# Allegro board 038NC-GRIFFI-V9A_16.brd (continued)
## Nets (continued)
N05396: UNK2K6.4 UNK2R3.1
N05400: UNK2K5.4 UNK2R2.1
N05404: UNK2R41.2 UNK2R42.1
N05614: UNK2C5.1 UNK2K8.5
N05638: UNK2C3.1 UNK2K2.4
N05774: UNK2C4.2 UNK2K8.4
N05938: SITE2.S24(PVSS_S) UNK2RS2.2 UNK2RS4.2
N05964: UNK2R14.1 UNK2SH7.1 UNK2SH9.2 UNK2SH14.2 UNK2SH16.2 UNK2SH30.1 UNK2SH32.2
N05980: UNK2R13.1 UNK2SH2.1 UNK2SH20.1 UNK2SH29.1 UNK2SH33.1 UNK2SH34.1 UNK2SH39.2
N10483: UNK3K7.4 UNK3R41.1
N10487: UNK3K6.4 UNK3R3.1
N10491: UNK3K5.4 UNK3R2.1
N10495: UNK3R41.2 UNK3R42.1
N10705: UNK3C5.1 UNK3K8.5
N10729: UNK3C3.1 UNK3K2.4
N10865: UNK3C4.2 UNK3K8.4
N11029: SITE3.S24(PVSS_S) UNK3RS2.2 UNK3RS4.2
N11055: UNK3R14.1 UNK3SH7.1 UNK3SH9.2 UNK3SH14.2 UNK3SH16.2 UNK3SH30.1 UNK3SH32.2
N11071: UNK3R13.1 UNK3SH2.1 UNK3SH20.1 UNK3SH29.1 UNK3SH33.1 UNK3SH34.1 UNK3SH39.2
N15574: UNK4K7.4 UNK4R41.1
N15578: UNK4K6.4 UNK4R3.1
N15582: UNK4K5.4 UNK4R2.1
N15586: UNK4R41.2 UNK4R42.1
N15796: UNK4C5.1 UNK4K8.5
N15820: UNK4C3.1 UNK4K2.4
N15956: UNK4C4.2 UNK4K8.4
N16120: SITE4.S24(PVSS_S) UNK4RS2.2 UNK4RS4.2
N16146: UNK4R14.1 UNK4SH7.1 UNK4SH9.2 UNK4SH14.2 UNK4SH16.2 UNK4SH30.1 UNK4SH32.2
N16162: UNK4R13.1 UNK4SH2.1 UNK4SH20.1 UNK4SH29.1 UNK4SH33.1 UNK4SH34.1 UNK4SH39.2
N20665: UNK5K7.4 UNK5R41.1
N20669: UNK5K6.4 UNK5R3.1
N20673: UNK5K5.4 UNK5R2.1
N20677: UNK5R41.2 UNK5R42.1
N20887: UNK5C5.1 UNK5K8.5
N20911: UNK5C3.1 UNK5K2.4
N21047: UNK5C4.2 UNK5K8.4
N21211: SITE5.S24(PVSS_S) UNK5RS2.2 UNK5RS4.2
N21237: UNK5R14.1 UNK5SH7.1 UNK5SH9.2 UNK5SH14.2 UNK5SH16.2 UNK5SH30.1 UNK5SH32.2
N21253: UNK5R13.1 UNK5SH2.1 UNK5SH20.1 UNK5SH29.1 UNK5SH33.1 UNK5SH34.1 UNK5SH39.2
N25756: UNK6K7.4 UNK6R41.1
N25760: UNK6K6.4 UNK6R3.1
N25764: UNK6K5.4 UNK6R2.1
N25768: UNK6R41.2 UNK6R42.1
N25978: UNK6C5.1 UNK6K8.5
N26002: UNK6C3.1 UNK6K2.4
N26138: UNK6C4.2 UNK6K8.4
N26302: SITE6.S24(PVSS_S) UNK6RS2.2 UNK6RS4.2
N26328: UNK6R14.1 UNK6SH7.1 UNK6SH9.2 UNK6SH14.2 UNK6SH16.2 UNK6SH30.1 UNK6SH32.2
N26344: UNK6R13.1 UNK6SH2.1 UNK6SH20.1 UNK6SH29.1 UNK6SH33.1 UNK6SH34.1 UNK6SH39.2
N30847: UNK7K7.4 UNK7R41.1
N30851: UNK7K6.4 UNK7R3.1
N30855: UNK7K5.4 UNK7R2.1
N30859: UNK7R41.2 UNK7R42.1
N31069: UNK7C5.1 UNK7K8.5
N31093: UNK7C3.1 UNK7K2.4
N31229: UNK7C4.2 UNK7K8.4
N31393: SITE7.S24(PVSS_S) UNK7RS2.2 UNK7RS4.2
N31419: UNK7R14.1 UNK7SH7.1 UNK7SH9.2 UNK7SH14.2 UNK7SH16.2 UNK7SH30.1 UNK7SH32.2
N31435: UNK7R13.1 UNK7SH2.1 UNK7SH20.1 UNK7SH29.1 UNK7SH33.1 UNK7SH34.1 UNK7SH39.2
N35938: UNK8K7.4 UNK8R41.1
N35942: UNK8K6.4 UNK8R3.1
N35946: UNK8K5.4 UNK8R2.1
N35950: UNK8R41.2 UNK8R42.1
N36160: UNK8C5.1 UNK8K8.5
N36184: UNK8C3.1 UNK8K2.4
N36320: UNK8C4.2 UNK8K8.4
N36484: SITE8.S24(PVSS_S) UNK8RS2.2 UNK8RS4.2
N36510: UNK8R14.1 UNK8SH7.1 UNK8SH9.2 UNK8SH14.2 UNK8SH16.2 UNK8SH30.1 UNK8SH32.2
N36526: UNK8R13.1 UNK8SH2.1 UNK8SH20.1 UNK8SH29.1 UNK8SH33.1 UNK8SH34.1 UNK8SH39.2
N41029: UNK9K7.4 UNK9R41.1
N41033: UNK9K6.4 UNK9R3.1
N41037: UNK9K5.4 UNK9R2.1
N41041: UNK9R41.2 UNK9R42.1
N41251: UNK9C5.1 UNK9K8.5
N41275: UNK9C3.1 UNK9K2.4
N41411: UNK9C4.2 UNK9K8.4
N41575: SITE9.S24(PVSS_S) UNK9RS2.2 UNK9RS4.2
N41601: UNK9R14.1 UNK9SH7.1 UNK9SH9.2 UNK9SH14.2 UNK9SH16.2 UNK9SH30.1 UNK9SH32.2
N41617: UNK9R13.1 UNK9SH2.1 UNK9SH20.1 UNK9SH29.1 UNK9SH33.1 UNK9SH34.1 UNK9SH39.2
N46120: UNK10K7.4 UNK10R41.1
N46124: UNK10K6.4 UNK10R3.1
N46128: UNK10K5.4 UNK10R2.1
N46132: UNK10R41.2 UNK10R42.1
N46342: UNK10C5.1 UNK10K8.5
N46366: UNK10C3.1 UNK10K2.4
N46502: UNK10C4.2 UNK10K8.4
N46666: SITE10.S24(PVSS_S) UNK10RS2.2 UNK10RS4.2
N46692: UNK10R14.1 UNK10SH7.1 UNK10SH9.2 UNK10SH14.2 UNK10SH16.2 UNK10SH30.1 UNK10SH32.2
N46708: UNK10R13.1 UNK10SH2.1 UNK10SH20.1 UNK10SH29.1 UNK10SH33.1 UNK10SH34.1 UNK10SH39.2
N51211: UNK11K7.4 UNK11R41.1
N51215: UNK11K6.4 UNK11R3.1
N51219: UNK11K5.4 UNK11R2.1
N51223: UNK11R41.2 UNK11R42.1
N51433: UNK11C5.1 UNK11K8.5
N51457: UNK11C3.1 UNK11K2.4
N51593: UNK11C4.2 UNK11K8.4
N51757: SITE11.S24(PVSS_S) UNK11RS2.2 UNK11RS4.2
N51783: UNK11R14.1 UNK11SH7.1 UNK11SH9.2 UNK11SH14.2 UNK11SH16.2 UNK11SH30.1 UNK11SH32.2
N51799: UNK11R13.1 UNK11SH2.1 UNK11SH20.1 UNK11SH29.1 UNK11SH33.1 UNK11SH34.1 UNK11SH39.2
N56302: UNK12K7.4 UNK12R41.1
N56306: UNK12K6.4 UNK12R3.1
N56310: UNK12K5.4 UNK12R2.1
N56314: UNK12R41.2 UNK12R42.1
N56524: UNK12C5.1 UNK12K8.5
N56548: UNK12C3.1 UNK12K2.4
N56684: UNK12C4.2 UNK12K8.4
N56848: SITE12.S24(PVSS_S) UNK12RS2.2 UNK12RS4.2
N56874: UNK12R14.1 UNK12SH7.1 UNK12SH9.2 UNK12SH14.2 UNK12SH16.2 UNK12SH30.1 UNK12SH32.2
N56890: UNK12R13.1 UNK12SH2.1 UNK12SH20.1 UNK12SH29.1 UNK12SH33.1 UNK12SH34.1 UNK12SH39.2
N61393: UNK13K7.4 UNK13R41.1
N61397: UNK13K6.4 UNK13R3.1
N61401: UNK13K5.4 UNK13R2.1
N61405: UNK13R41.2 UNK13R42.1
N61615: UNK13C5.1 UNK13K8.5
N61639: UNK13C3.1 UNK13K2.4
N61775: UNK13C4.2 UNK13K8.4
N61939: SITE13.S24(PVSS_S) UNK13RS2.2 UNK13RS4.2
N61965: UNK13R14.1 UNK13SH7.1 UNK13SH9.2 UNK13SH14.2 UNK13SH16.2 UNK13SH30.1 UNK13SH32.2
N61981: UNK13R13.1 UNK13SH2.1 UNK13SH20.1 UNK13SH29.1 UNK13SH33.1 UNK13SH34.1 UNK13SH39.2
N66484: UNK14K7.4 UNK14R41.1
N66488: UNK14K6.4 UNK14R3.1
N66492: UNK14K5.4 UNK14R2.1
N66496: UNK14R41.2 UNK14R42.1
N66706: UNK14C5.1 UNK14K8.5
N66730: UNK14C3.1 UNK14K2.4
N66866: UNK14C4.2 UNK14K8.4
N67030: SITE14.S24(PVSS_S) UNK14RS2.2 UNK14RS4.2
N67056: UNK14R14.1 UNK14SH7.1 UNK14SH9.2 UNK14SH14.2 UNK14SH16.2 UNK14SH30.1 UNK14SH32.2
N67072: UNK14R13.1 UNK14SH2.1 UNK14SH20.1 UNK14SH29.1 UNK14SH33.1 UNK14SH34.1 UNK14SH39.2
N71575: UNK15K7.4 UNK15R41.1
N71579: UNK15K6.4 UNK15R3.1
N71583: UNK15K5.4 UNK15R2.1
N71587: UNK15R41.2 UNK15R42.1
N71797: UNK15C5.1 UNK15K8.5
N71821: UNK15C3.1 UNK15K2.4
N71957: UNK15C4.2 UNK15K8.4
N72121: SITE15.S24(PVSS_S) UNK15RS2.2 UNK15RS4.2
N72147: UNK15R14.1 UNK15SH7.1 UNK15SH9.2 UNK15SH14.2 UNK15SH16.2 UNK15SH30.1 UNK15SH32.2
N72163: UNK15R13.1 UNK15SH2.1 UNK15SH20.1 UNK15SH29.1 UNK15SH33.1 UNK15SH34.1 UNK15SH39.2
N76666: UNK16K7.4 UNK16R41.1
N76670: UNK16K6.4 UNK16R3.1
N76674: UNK16K5.4 UNK16R2.1
N76678: UNK16R41.2 UNK16R42.1
N76888: UNK16C5.1 UNK16K8.5
N76912: UNK16C3.1 UNK16K2.4
N77048: UNK16C4.2 UNK16K8.4
N77212: SITE16.S24(PVSS_S) UNK16RS2.2 UNK16RS4.2
N77238: UNK16R14.1 UNK16SH7.1 UNK16SH9.2 UNK16SH14.2 UNK16SH16.2 UNK16SH30.1 UNK16SH32.2
N77254: UNK16R13.1 UNK16SH2.1 UNK16SH20.1 UNK16SH29.1 UNK16SH33.1 UNK16SH34.1 UNK16SH39.2
N19416570: UNK1K7.4 UNK1R41.1
N19416573: UNK1K6.4 UNK1R3.1
N19416576: UNK1K5.4 UNK1R2.1
N19416583: UNK1R41.2 UNK1R42.1
N19419031: UNK1C5.1 UNK1K8.5
N19465903: UNK1C3.1 UNK1K2.4
N19474263: UNK1C4.2 UNK1K8.4
N19657625: SITE1.S24(PVSS_S) UNK1RS2.2 UNK1RS4.2
N19659235: UNK1R14.1 UNK1SH7.1 UNK1SH9.2 UNK1SH14.2 UNK1SH16.2 UNK1SH30.1 UNK1SH32.2
N19659515: UNK1R13.1 UNK1SH2.1 UNK1SH20.1 UNK1SH29.1 UNK1SH33.1 UNK1SH34.1 UNK1SH39.2
N22962297: BR4.1 USER_12V1.2(B)
N22962300: BR1.1 USER_5V1.2(B)
N22962303: BR2.1 USER_-5V1.2(B)
N22962306: BR3.1 RLY_5V1.2(B)

Pads without a net: FD1 1; FD2 1; FD3 1; FD4 1; FD5 1; FD6 1; FD7 1; FD8 1; FD9 1; FD10 1; FD11 1; FD12 1; FD13 1; FD14 1; FD15 1; FD16 1; LOGO1 1; LOGO2 1; NPM1212-GRIFFI 1; NPM1212-QFN28-P0.4 1; SITE1 NUT1 NUT2 NUT3 NUT4; SITE2 NUT1 NUT2 NUT3 NUT4; SITE3 NUT1 NUT2 NUT3 NUT4; SITE4 NUT1 NUT2 NUT3 NUT4; SITE5 NUT1 NUT2 NUT3 NUT4; SITE6 NUT1 NUT2 NUT3 NUT4; SITE7 NUT1 NUT2 NUT3 NUT4; SITE8 NUT1 NUT2 NUT3 NUT4; SITE9 NUT1 NUT2 NUT3 NUT4; SITE10 NUT1 NUT2 NUT3 NUT4; SITE11 NUT1 NUT2 NUT3 NUT4; SITE12 NUT1 NUT2 NUT3 NUT4; SITE13 NUT1 NUT2 NUT3 NUT4; SITE14 NUT1 NUT2 NUT3 NUT4; SITE15 NUT1 NUT2 NUT3 NUT4; SITE16 NUT1 NUT2 NUT3 NUT4; SLOT0 A1 A48 B1 C1 D1 E1 F1 G48 Z5 Z7 Z9 Z11 Z13 Z15 Z17 Z19 Z21 Z23 Z25 Z27 Z29 Z31 Z33 Z35 Z37 Z39 Z41 Z43 Z45 Z47 Z49 Z51 Z53 Z55 Z57 Z59 Z61; SLOT1 A1 A2 A3 A4 A5 A6 A7 A8 A9 A10 A11 A12 A13 A14 A15 A16 A17 A18 A19 A20 A21 A22 A23 A24 A25 A26 A27 A28 A29 A30 A31 A32 A33 A34 A35 A36 A37 A38 A39 A40 A41 A42 A43 A44 A45 A46 A47 A48 A49 A50 A51 A52 A53 A54 A55 A56 A57 A58 A59 A60 A61 B1 B2 B3 B4 B5 B6 B7 B8 B9 B10 B11 B12 B13 B14 B15 B16 B17 B18 B19 B20 B21 B22 B23 B24 B25 B26 B27 B28 B29 B30 B31 B32 B33 B34 B35 B36 B37 B38 B39 B40 B41 B42 B43 B44 B45 B46 B47 B48 B49 B50 B51 B52 B53 B54 B55 B56 B57 B58 B59 B60 B61 B62 C1 C2 C3 C4 C5 C6 C7 C8 C9 C10 C11 C12 C13 C14 C15 C16 C17 C18 C19 C20 C21 C22 C23 C24 C25 C26 C27 C28 C29 C30 C31 C32 C33 C34 C35 C36 C37 C38 C39 C40 C41 C42 C43 C44 C45 C46 C47 C48 C49 C50 C51 C52 C53 C54 C55 C56 C57 C58 C59 C60 C61 C62 D1 D2 D3 D4 D5 D6 D7 D8 D9 D10 D11 D12 D13 D14 D15 D16 D17 D18 D19 D20 D21 D22 D23 D24 D25 D26 D27 D28 D29 D30 D31 D32 D33 D34 D35 D36 D37 D38 D39 D40 D41 D42 D43 D44 D45 D46 D47 D48 D49 D50 D51 D52 D53 D54 D55 D56 D57 D58 D59 D60 D61 E1 E2 E3 E4 E5 E6 E7 E8 E9 E10 E11 E12 E13 E14 E15 E16 E17 E18 E19 E20 E21 E22 E23 E24 E25 E26 E27 E28 E29 E30 E31 E32 E33 E34 E35 E36 E37 E38 E39 E40 E41 E42 E43 E44 E45 E46 E47 E48 E49 E50 E51 E52 E53 E54 E55 E56 E57 E58 E59 E60 E61 E62 F1 F2 F3 F4 F5 F6 F7 F8 F9 F10 F11 F12 F13 F14 F15 F16 F17 F18 F19 F20 F21 F22 F23 F24 F25 F26 F27 F28 F29 F30 F31 F32 F33 F34 F35 F36 F37 F38 F39 F40 F41 F42 F43 F44 F45 F46 F47 F48 F49 F50 F51 F52 F53 F54 F55 F56 F57 F58 F59 F60 F61 F62 G2 G4 G6 G8 G10 G12 G14 G16 G18 G20 G22 G24 G26 G28 G30 G32 G34 G36 G38 G40 G42 G44 G46 G48 G50 G52 G54 G56 G58 G60 Z5 Z7 Z9 Z11 Z13 Z15 Z17 Z19 Z21 Z23 Z25 Z27 Z29 Z31 Z33 Z35 Z37 Z39 Z41 Z43 Z45 Z47 Z49 Z51 Z53 Z55 Z57 Z59 Z61; SLOT2 A1 A2 A3 A4 A5 A6 A7 A8 A9 A10 A11 A12 A13 A14 A15 A16 A17 A18 A19 A20 A21 A22 A23 A24 A25 A26 A27 A28 A29 A30 A31 A32 A33 A34 A35 A36 A37 A38 A39 A40 A41 A42 A43 A44 A45 A46 A47 A48 A49 A50 A51 A52 A53 A54 A55 A56 A57 A58 A59 A60 A61 B1 B2 B3 B4 B5 B6 B7 B8 B9 B10 B11 B12 B13 B14 B15 B16 B17 B18 B19 B20 B21 B22 B23 B24 B25 B26 B27 B28 B29 B30 B31 B32 B33 B34 B35 B36 B37 B38 B39 B40 B41 B42 B43 B44 B45 B46 B47 B48 B49 B50 B51 B52 B53 B54 B55 B56 B57 B58 B59 B60 B61 B62 C1 C2 C3 C4 C5 C6 C7 C8 C9 C10 C11 C12 C13 C14 C15 C16 C17 C18 C19 C20 C21 C22 C23 C24 C25 C26 C27 C28 C29 C30 C31 C32 C33 C34 C35 C36 C37 C38 C39 C40 C41 C42 C43 C44 C45 C46 C47 C48 C49 C50 C51 C52 C53 C54 C55 C56 C57 C58 C59 C60 C61 C62 D1 D2 D3 D4 D5 D6 D7 D8 D9 D10 D11 D12 D13 D14 D15 D16 D17 D18 D19 D20 D21 D22 D23 D24 D25 D26 D27 D28 D29 D30 D31 D32 D33 D34 D35 D36 D37 D38 D39 D40 D41 D42 D43 D44 D45 D46 D47 D48 D49 D50 D51 D52 D53 D54 D55 D56 D57 D58 D59 D60 D61 E1 E2 E3 E4 E5 E6 E7 E8 E9 E10 E11 E12 E13 E14 E15 E16 E17 E18 E19 E20 E21 E22 E23 E24 E25 E26 E27 E28 E29 E30 E31 E32 E33 E34 E35 E36 E37 E38 E39 E40 E41 E42 E43 E44 E45 E46 E47 E48 E49 E50 E51 E52 E53 E54 E55 E56 E57 E58 E59 E60 E61 E62 F1 F2 F3 F4 F5 F6 F7 F8 F9 F10 F11 F12 F13 F14 F15 F16 F17 F18 F19 F20 F21 F22 F23 F24 F25 F26 F27 F28 F29 F30 F31 F32 F33 F34 F35 F36 F37 F38 F39 F40 F41 F42 F43 F44 F45 F46 F47 F48 F49 F50 F51 F52 F53 F54 F55 F56 F57 F58 F59 F60 F61 F62 G2 G4 G6 G8 G10 G12 G14 G16 G18 G20 G22 G24 G26 G28 G30 G32 G34 G36 G38 G40 G42 G44 G46 G48 G50 G52 G54 G56 G58 G60 Z5 Z7 Z9 Z11 Z13 Z15 Z17 Z19 Z21 Z23 Z25 Z27 Z29 Z31 Z33 Z35 Z37 Z39 Z41 Z43 Z45 Z47 Z49 Z51 Z53 Z55 Z57 Z59 Z61; SLOT3 A1 A2 A3 A4 A19 A61 B1 B2 B3 B4 B61 B62 C1 C2 C3 C4 C62 D1 D2 D3 D4 D19 E1 E2 E3 E4 E19 E62 F1 F2 F3 F4 F62 G2 G4 G6 G8 G10 G12 G14 G16 G18 G20 G22 G24 G26 G28 G30 G32 G34 G36 G38 G40 G42 G44 G46 G48 G50 G52 G54 G56 G58 G60 Z17 Z19 Z37 Z51 Z61; SLOT4 A1 A2 A3 A4 A19 A61 B1 B2 B3 B4 B61 B62 C1 C2 C3 C4 C62 D1 D2 D3 D4 D19 E1 E2 E3 E4 E19 E62 F1 F2 F3 F4 F62 G2 G4 G6 G8 G10 G12 G14 G16 G18 G20 G22 G24 G26 G28 G30 G32 G34 G36 G38 G40 G42 G44 G46 G48 G50 G52 G54 G56 G58 G60 Z17 Z19 Z37 Z51 Z61; SLOT5 A1 A2 A3 A4 A5 A6 A7 A8 A9 A10 A11 A12 A13 A14 A15 A16 A17 A18 A19 A20 A21 A22 A23 A24 A25 A26 A27 A28 A29 A30 A31 A32 A33 A34 A35 A36 A37 A38 A39 A40 A41 A42 A43 A44 A45 A46 A47 A48 A49 A50 A51 A52 A53 A54 A55 A56 A57 A58 A59 A60 A61 B1 B2 B3 B4 B5 B6 B7 B8 B9 B10 B11 B12 B13 B14 B15 B16 B17 B18 B19 B20 B21 B22 B23 B24 B25 B26 B27 B28 B29 B30 B31 B32 B33 B34 B35 B36 B37 B38 B39 B40 B41 B42 B43 B44 B45 B46 B47 B48 B49 B50 B51 B52 B53 B54 B55 B56 B57 B58 B59 B60 B61 B62 C1 C2 C3 C4 C5 C6 C7 C8 C9 C10 C11 C12 C13 C14 C15 C16 C17 C18 C19 C20 C21 C22 C23 C24 C25 C26 C27 C28 C29 C30 C31 C32 C33 C34 C35 C36 C37 C38 C39 C40 C41 C42 C43 C44 C45 C46 C47 C48 C49 C50 C51 C52 C53 C54 C55 C56 C57 C58 C59 C60 C61 C62 D1 D2 D3 D4 D5 D6 D7 D8 D9 D10 D11 D12 D13 D14 D15 D16 D17 D18 D19 D20 D21 D22 D23 D24 D25 D26 D27 D28 D29 D30 D31 D32 D33 D34 D35 D36 D37 D38 D39 D40 D41 D42 D43 D44 D45 D46 D47 D48 D49 D50 D51 D52 D53 D54 D55 D56 D57 D58 D59 D60 D61 E1 E2 E3 E4 E5 E6 E7 E8 E9 E10 E11 E12 E13 E14 E15 E16 E17 E18 E19 E20 E21 E22 E23 E24 E25 E26 E27 E28 E29 E30 E31 E32 E33 E34 E35 E36 E37 E38 E39 E40 E41 E42 E43 E44 E45 E46 E47 E48 E49 E50 E51 E52 E53 E54 E55 E56 E57 E58 E59 E60 E61 E62 F1 F2 F3 F4 F5 F6 F7 F8 F9 F10 F11 F12 F13 F14 F15 F16 F17 F18 F19 F20 F21 F22 F23 F24 F25 F26 F27 F28 F29 F30 F31 F32 F33 F34 F35 F36 F37 F38 F39 F40 F41 F42 F43 F44 F45 F46 F47 F48 F49 F50 F51 F52 F53 F54 F55 F56 F57 F58 F59 F60 F61 F62 G2 G4 G6 G8 G10 G12 G14 G16 G18 G20 G22 G24 G26 G28 G30 G32 G34 G36 G38 G40 G42 G44 G46 G48 G50 G52 G54 G56 G58 G60 Z5 Z7 Z9 Z11 Z13 Z15 Z17 Z19 Z21 Z23 Z25 Z27 Z29 Z31 Z33 Z35 Z37 Z39 Z41 Z43 Z45 Z47 Z49 Z51 Z53 Z55 Z57 Z59 Z61; SLOT6 B6 D6 D23 D27 D31 D35 E4 Z5 Z7 Z9 Z11 Z13 Z15 Z17 Z19 Z21 Z23 Z25 Z27 Z29 Z31 Z33 Z35 Z37 Z39 Z41 Z43 Z45 Z47 Z49 Z51 Z53 Z55 Z57 Z59 Z61; SLOT7 B6 D6 D23 D27 D31 D35 E4 Z5 Z7 Z9 Z11 Z13 Z15 Z17 Z19 Z21 Z23 Z25 Z27 Z29 Z31 Z33 Z35 Z37 Z39 Z41 Z43 Z45 Z47 Z49 Z51 Z53 Z55 Z57 Z59 Z61; SLOT8 B6 D6 D23 D27 D31 D35 E4 Z5 Z7 Z9 Z11 Z13 Z15 Z17 Z19 Z21 Z23 Z25 Z27 Z29 Z31 Z33 Z35 Z37 Z39 Z41 Z43 Z45 Z47 Z49 Z51 Z53 Z55 Z57 Z59 Z61; SLOT9 B6 D6 D23 D27 D31 D35 E4 Z5 Z7 Z9 Z11 Z13 Z15 Z17 Z19 Z21 Z23 Z25 Z27 Z29 Z31 Z33 Z35 Z37 Z39 Z41 Z43 Z45 Z47 Z49 Z51 Z53 Z55 Z57 Z59 Z61; SLOT10 B6 D6 D23 D27 D31 D35 E4 Z5 Z7 Z9 Z11 Z13 Z15 Z17 Z19 Z21 Z23 Z25 Z27 Z29 Z31 Z33 Z35 Z37 Z39 Z41 Z43 Z45 Z47 Z49 Z51 Z53 Z55 Z57 Z59 Z61; SLOT11 A1 A2 A3 A4 A5 A6 A7 A8 A9 A10 A11 A12 A13 A14 A15 A16 A17 A18 A19 A20 A21 A22 A23 A24 A25 A26 A27 A28 A29 A30 A31 A32 A33 A34 A35 A36 A37 A38 A39 A40 A41 A42 A43 A44 A45 A46 A47 A48 A49 A50 A51 A52 A53 A54 A55 A56 A57 A58 A59 A60 A61 B1 B2 B3 B4 B5 B6 B7 B8 B9 B10 B11 B12 B13 B14 B15 B16 B17 B18 B19 B20 B21 B22 B23 B24 B25 B26 B27 B28 B29 B30 B31 B32 B33 B34 B35 B36 B37 B38 B39 B40 B41 B42 B43 B44 B45 B46 B47 B48 B49 B50 B51 B52 B53 B54 B55 B56 B57 B58 B59 B60 B61 B62 C1 C2 C3 C4 C5 C6 C7 C8 C9 C10 C11 C12 C13 C14 C15 C16 C17 C18 C19 C20 C21 C22 C23 C24 C25 C26 C27 C28 C29 C30 C31 C32 C33 C34 C35 C36 C37 C38 C39 C40 C41 C42 C43 C44 C45 C46 C47 C48 C49 C50 C51 C52 C53 C54 C55 C56 C57 C58 C59 C60 C61 C62 D1 D2 D3 D4 D5 D6 D7 D8 D9 D10 D11 D12 D13 D14 D15 D16 D17 D18 D19 D20 D21 D22 D23 D24 D25 D26 D27 D28 D29 D30 D31 D32 D33 D34 D35 D36 D37 D38 D39 D40 D41 D42 D43 D44 D45 D46 D47 D48 D49 D50 D51 D52 D53 D54 D55 D56 D57 D58 D59 D60 D61 E1 E2 E3 E4 E5 E6 E7 E8 E9 E10 E11 E12 E13 E14 E15 E16 E17 E18 E19 E20 E21 E22 E23 E24 E25 E26 E27 E28 E29 E30 E31 E32 E33 E34 E35 E36 E37 E38 E39 E40 E41 E42 E43 E44 E45 E46 E47 E48 E49 E50 E51 E52 E53 E54 E55 E56 E57 E58 E59 E60 E61 E62 F1 F2 F3 F4 F5 F6 F7 F8 F9 F10 F11 F12 F13 F14 F15 F16 F17 F18 F19 F20 F21 F22 F23 F24 F25 F26 F27 F28 F29 F30 F31 F32 F33 F34 F35 F36 F37 F38 F39 F40 F41 F42 F43 F44 F45 F46 F47 F48 F49 F50 F51 F52 F53 F54 F55 F56 F57 F58 F59 F60 F61 F62 G2 G4 G6 G8 G10 G12 G14 G16 G18 G20 G22 G24 G26 G28 G30 G32 G34 G36 G38 G40 G42 G44 G46 G48 G50 G52 G54 G56 G58 G60 Z5 Z7 Z9 Z11 Z13 Z15 Z17 Z19 Z21 Z23 Z25 Z27 Z29 Z31 Z33 Z35 Z37 Z39 Z41 Z43 Z45 Z47 Z49 Z51 Z53 Z55 Z57 Z59 Z61; SLOT12 A1 A2 A3 A4 A5 A6 A7 A8 A9 A10 A11 A12 A13 A14 A15 A16 A17 A18 A19 A20 A21 A22 A23 A24 A25 A26 A27 A28 A29 A30 A31 A32 A33 A34 A35 A36 A37 A38 A39 A40 A41 A42 A43 A44 A45 A46 A47 A48 A49 A50 A51 A52 A53 A54 A55 A56 A57 A58 A59 A60 A61 B1 B2 B3 B4 B5 B6 B7 B8 B9 B10 B11 B12 B13 B14 B15 B16 B17 B18 B19 B20 B21 B22 B23 B24 B25 B26 B27 B28 B29 B30 B31 B32 B33 B34 B35 B36 B37 B38 B39 B40 B41 B42 B43 B44 B45 B46 B47 B48 B49 B50 B51 B52 B53 B54 B55 B56 B57 B58 B59 B60 B61 B62 C1 C2 C3 C4 C5 C6 C7 C8 C9 C10 C11 C12 C13 C14 C15 C16 C17 C18 C19 C20 C21 C22 C23 C24 C25 C26 C27 C28 C29 C30 C31 C32 C33 C34 C35 C36 C37 C38 C39 C40 C41 C42 C43 C44 C45 C46 C47 C48 C49 C50 C51 C52 C53 C54 C55 C56 C57 C58 C59 C60 C61 C62 D1 D2 D3 D4 D5 D6 D7 D8 D9 D10 D11 D12 D13 D14 D15 D16 D17 D18 D19 D20 D21 D22 D23 D24 D25 D26 D27 D28 D29 D30 D31 D32 D33 D34 D35 D36 D37 D38 D39 D40 D41 D42 D43 D44 D45 D46 D47 D48 D49 D50 D51 D52 D53 D54 D55 D56 D57 D58 D59 D60 D61 E1 E2 E3 E4 E5 E6 E7 E8 E9 E10 E11 E12 E13 E14 E15 E16 E17 E18 E19 E20 E21 E22 E23 E24 E25 E26 E27 E28 E29 E30 E31 E32 E33 E34 E35 E36 E37 E38 E39 E40 E41 E42 E43 E44 E45 E46 E47 E48 E49 E50 E51 E52 E53 E54 E55 E56 E57 E58 E59 E60 E61 E62 F1 F2 F3 F4 F5 F6 F7 F8 F9 F10 F11 F12 F13 F14 F15 F16 F17 F18 F19 F20 F21 F22 F23 F24 F25 F26 F27 F28 F29 F30 F31 F32 F33 F34 F35 F36 F37 F38 F39 F40 F41 F42 F43 F44 F45 F46 F47 F48 F49 F50 F51 F52 F53 F54 F55 F56 F57 F58 F59 F60 F61 F62 G2 G4 G6 G8 G10 G12 G14 G16 G18 G20 G22 G24 G26 G28 G30 G32 G34 G36 G38 G40 G42 G44 G46 G48 G50 G52 G54 G56 G58 G60 Z5 Z7 Z9 Z11 Z13 Z15 Z17 Z19 Z21 Z23 Z25 Z27 Z29 Z31 Z33 Z35 Z37 Z39 Z41 Z43 Z45 Z47 Z49 Z51 Z53 Z55 Z57 Z59 Z61; SLOT13 B6 D6 D23 D27 D31 D35 E4 Z5 Z7 Z9 Z11 Z13 Z15 Z17 Z19 Z21 Z23 Z25 Z27 Z29 Z31 Z33 Z35 Z37 Z39 Z41 Z43 Z45 Z47 Z49 Z51 Z53 Z55 Z57 Z59 Z61; SLOT14 A1 A2 A3 A4 A5 A6 A7 A8 A9 A10 A11 A12 A13 A14 A15 A16 A17 A18 A19 A20 A21 A22 A23 A24 A25 A26 A27 A28 A29 A30 A31 A32 A33 A34 A35 A36 A37 A38 A39 A40 A41 A42 A43 A44 A45 A46 A47 A48 A49 A50 A51 A52 A53 A54 A55 A56 A57 A58 A59 A60 A61 B1 B2 B3 B4 B5 B6 B7 B8 B9 B10 B11 B12 B13 B14 B15 B16 B17 B18 B19 B20 B21 B22 B23 B24 B25 B26 B27 B28 B29 B30 B31 B32 B33 B34 B35 B36 B37 B38 B39 B40 B41 B42 B43 B44 B45 B46 B47 B48 B49 B50 B51 B52 B53 B54 B55 B56 B57 B58 B59 B60 B61 B62 C1 C2 C3 C4 C5 C6 C7 C8 C9 C10 C11 C12 C13 C14 C15 C16 C17 C18 C19 C20 C21 C22 C23 C24 C25 C26 C27 C28 C29 C30 C31 C32 C33 C34 C35 C36 C37 C38 C39 C40 C41 C42 C43 C44 C45 C46 C47 C48 C49 C50 C51 C52 C53 C54 C55 C56 C57 C58 C59 C60 C61 C62 D1 D2 D3 D4 D5 D6 D7 D8 D9 D10 D11 D12 D13 D14 D15 D16 D17 D18 D19 D20 D21 D22 D23 D24 D25 D26 D27 D28 D29 D30 D31 D32 D33 D34 D35 D36 D37 D38 D39 D40 D41 D42 D43 D44 D45 D46 D47 D48 D49 D50 D51 D52 D53 D54 D55 D56 D57 D58 D59 D60 D61 E1 E2 E3 E4 E5 E6 E7 E8 E9 E10 E11 E12 E13 E14 E15 E16 E17 E18 E19 E20 E21 E22 E23 E24 E25 E26 E27 E28 E29 E30 E31 E32 E33 E34 E35 E36 E37 E38 E39 E40 E41 E42 E43 E44 E45 E46 E47 E48 E49 E50 E51 E52 E53 E54 E55 E56 E57 E58 E59 E60 E61 E62 F1 F2 F3 F4 F5 F6 F7 F8 F9 F10 F11 F12 F13 F14 F15 F16 F17 F18 F19 F20 F21 F22 F23 F24 F25 F26 F27 F28 F29 F30 F31 F32 F33 F34 F35 F36 F37 F38 F39 F40 F41 F42 F43 F44 F45 F46 F47 F48 F49 F50 F51 F52 F53 F54 F55 F56 F57 F58 F59 F60 F61 F62 G2 G4 G6 G8 G10 G12 G14 G16 G18 G20 G22 G24 G26 G28 G30 G32 G34 G36 G38 G40 G42 G44 G46 G48 G50 G52 G54 G56 G58 G60 Z5 Z7 Z9 Z11 Z13 Z15 Z17 Z19 Z21 Z23 Z25 Z27 Z29 Z31 Z33 Z35 Z37 Z39 Z41 Z43 Z45 Z47 Z49 Z51 Z53 Z55 Z57 Z59 Z61; SLOT15 A1 A2 A3 A4 A5 A6 A7 A8 A9 A10 A11 A12 A13 A14 A15 A16 A17 A18 A19 A20 A21 A22 A23 A24 A25 A26 A27 A28 A29 A30 A31 A32 A33 A34 A35 A36 A37 A38 A39 A40 A41 A42 A43 A44 A45 A46 A47 A48 A49 A50 A51 A52 A53 A54 A55 A56 A57 A58 A59 A60 A61 B1 B2 B3 B4 B5 B6 B7 B8 B9 B10 B11 B12 B13 B14 B15 B16 B17 B18 B19 B20 B21 B22 B23 B24 B25 B26 B27 B28 B29 B30 B31 B32 B33 B34 B35 B36 B37 B38 B39 B40 B41 B42 B43 B44 B45 B46 B47 B48 B49 B50 B51 B52 B53 B54 B55 B56 B57 B58 B59 B60 B61 B62 C1 C2 C3 C4 C5 C6 C7 C8 C9 C10 C11 C12 C13 C14 C15 C16 C17 C18 C19 C20 C21 C22 C23 C24 C25 C26 C27 C28 C29 C30 C31 C32 C33 C34 C35 C36 C37 C38 C39 C40 C41 C42 C43 C44 C45 C46 C47 C48 C49 C50 C51 C52 C53 C54 C55 C56 C57 C58 C59 C60 C61 C62 D1 D2 D3 D4 D5 D6 D7 D8 D9 D10 D11 D12 D13 D14 D15 D16 D17 D18 D19 D20 D21 D22 D23 D24 D25 D26 D27 D28 D29 D30 D31 D32 D33 D34 D35 D36 D37 D38 D39 D40 D41 D42 D43 D44 D45 D46 D47 D48 D49 D50 D51 D52 D53 D54 D55 D56 D57 D58 D59 D60 D61 E1 E2 E3 E4 E5 E6 E7 E8 E9 E10 E11 E12 E13 E14 E15 E16 E17 E18 E19 E20 E21 E22 E23 E24 E25 E26 E27 E28 E29 E30 E31 E32 E33 E34 E35 E36 E37 E38 E39 E40 E41 E42 E43 E44 E45 E46 E47 E48 E49 E50 E51 E52 E53 E54 E55 E56 E57 E58 E59 E60 E61 E62 F1 F2 F3 F4 F5 F6 F7 F8 F9 F10 F11 F12 F13 F14 F15 F16 F17 F18 F19 F20 F21 F22 F23 F24 F25 F26 F27 F28 F29 F30 F31 F32 F33 F34 F35 F36 F37 F38 F39 F40 F41 F42 F43 F44 F45 F46 F47 F48 F49 F50 F51 F52 F53 F54 F55 F56 F57 F58 F59 F60 F61 F62 G2 G4 G6 G8 G10 G12 G14 G16 G18 G20 G22 G24 G26 G28 G30 G32 G34 G36 G38 G40 G42 G44 G46 G48 G50 G52 G54 G56 G58 G60 Z5 Z7 Z9 Z11 Z13 Z15 Z17 Z19 Z21 Z23 Z25 Z27 Z29 Z31 Z33 Z35 Z37 Z39 Z41 Z43 Z45 Z47 Z49 Z51 Z53 Z55 Z57 Z59 Z61; SLOT16 A1 A2 A3 A4 A5 A6 A7 A8 A9 A10 A11 A12 A13 A14 A15 A16 A17 A18 A19 A20 A21 A22 A23 A24 A25 A26 A27 A28 A29 A30 A31 A32 A33 A34 A35 A36 A37 A38 A39 A40 A41 A42 A43 A44 A45 A46 A47 A48 A49 A50 A51 A52 A53 A54 A55 A56 A57 A58 A59 A60 A61 B1 B2 B3 B4 B5 B6 B7 B8 B9 B10 B11 B12 B13 B14 B15 B16 B17 B18 B19 B20 B21 B22 B23 B24 B25 B26 B27 B28 B29 B30 B31 B32 B33 B34 B35 B36 B37 B38 B39 B40 B41 B42 B43 B44 B45 B46 B47 B48 B49 B50 B51 B52 B53 B54 B55 B56 B57 B58 B59 B60 B61 B62 C1 C2 C3 C4 C5 C6 C7 C8 C9 C10 C11 C12 C13 C14 C15 C16 C17 C18 C19 C20 C21 C22 C23 C24 C25 C26 C27 C28 C29 C30 C31 C32 C33 C34 C35 C36 C37 C38 C39 C40 C41 C42 C43 C44 C45 C46 C47 C48 C49 C50 C51 C52 C53 C54 C55 C56 C57 C58 C59 C60 C61 C62 D1 D2 D3 D4 D5 D6 D7 D8 D9 D10 D11 D12 D13 D14 D15 D16 D17 D18 D19 D20 D21 D22 D23 D24 D25 D26 D27 D28 D29 D30 D31 D32 D33 D34 D35 D36 D37 D38 D39 D40 D41 D42 D43 D44 D45 D46 D47 D48 D49 D50 D51 D52 D53 D54 D55 D56 D57 D58 D59 D60 D61 E1 E2 E3 E4 E5 E6 E7 E8 E9 E10 E11 E12 E13 E14 E15 E16 E17 E18 E19 E20 E21 E22 E23 E24 E25 E26 E27 E28 E29 E30 E31 E32 E33 E34 E35 E36 E37 E38 E39 E40 E41 E42 E43 E44 E45 E46 E47 E48 E49 E50 E51 E52 E53 E54 E55 E56 E57 E58 E59 E60 E61 E62 F1 F2 F3 F4 F5 F6 F7 F8 F9 F10 F11 F12 F13 F14 F15 F16 F17 F18 F19 F20 F21 F22 F23 F24 F25 F26 F27 F28 F29 F30 F31 F32 F33 F34 F35 F36 F37 F38 F39 F40 F41 F42 F43 F44 F45 F46 F47 F48 F49 F50 F51 F52 F53 F54 F55 F56 F57 F58 F59 F60 F61 F62 G2 G4 G6 G8 G10 G12 G14 G16 G18 G20 G22 G24 G26 G28 G30 G32 G34 G36 G38 G40 G42 G44 G46 G48 G50 G52 G54 G56 G58 G60 Z5 Z7 Z9 Z11 Z13 Z15 Z17 Z19 Z21 Z23 Z25 Z27 Z29 Z31 Z33 Z35 Z37 Z39 Z41 Z43 Z45 Z47 Z49 Z51 Z53 Z55 Z57 Z59 Z61; SLOT17 A1 A2 A3 A4 A19 A61 B1 B2 B3 B4 B61 B62 C1 C2 C3 C4 C62 D1 D2 D3 D4 D19 E1 E2 E3 E4 E19 E62 F1 F2 F3 F4 F62 G2 G4 G6 G8 G10 G12 G14 G16 G18 G20 G22 G24 G26 G28 G30 G32 G34 G36 G38 G40 G42 G44 G46 G48 G50 G52 G54 G56 G58 G60 Z17 Z19 Z37 Z51 Z61; SLOT18 A1 A2 A3 A4 A5 A6 A7 A8 A9 A10 A11 A12 A13 A14 A15 A16 A17 A18 A19 A20 A21 A22 A23 A24 A25 A26 A27 A28 A29 A30 A31 A32 A33 A34 A35 A36 A37 A38 A39 A40 A41 A42 A43 A44 A45 A46 A47 A48 A49 A50 A51 A52 A53 A54 A55 A56 A57 A58 A59 A60 A61 B1 B2 B3 B4 B5 B6 B7 B8 B9 B10 B11 B12 B13 B14 B15 B16 B17 B18 B19 B20 B21 B22 B23 B24 B25 B26 B27 B28 B29 B30 B31 B32 B33 B34 B35 B36 B37 B38 B39 B40 B41 B42 B43 B44 B45 B46 B47 B48 B49 B50 B51 B52 B53 B54 B55 B56 B57 B58 B59 B60 B61 B62 C1 C2 C3 C4 C5 C6 C7 C8 C9 C10 C11 C12 C13 C14 C15 C16 C17 C18 C19 C20 C21 C22 C23 C24 C25 C26 C27 C28 C29 C30 C31 C32 C33 C34 C35 C36 C37 C38 C39 C40 C41 C42 C43 C44 C45 C46 C47 C48 C49 C50 C51 C52 C53 C54 C55 C56 C57 C58 C59 C60 C61 C62 D1 D2 D3 D4 D5 D6 D7 D8 D9 D10 D11 D12 D13 D14 D15 D16 D17 D18 D19 D20 D21 D22 D23 D24 D25 D26 D27 D28 D29 D30 D31 D32 D33 D34 D35 D36 D37 D38 D39 D40 D41 D42 D43 D44 D45 D46 D47 D48 D49 D50 D51 D52 D53 D54 D55 D56 D57 D58 D59 D60 D61 E1 E2 E3 E4 E5 E6 E7 E8 E9 E10 E11 E12 E13 E14 E15 E16 E17 E18 E19 E20 E21 E22 E23 E24 E25 E26 E27 E28 E29 E30 E31 E32 E33 E34 E35 E36 E37 E38 E39 E40 E41 E42 E43 E44 E45 E46 E47 E48 E49 E50 E51 E52 E53 E54 E55 E56 E57 E58 E59 E60 E61 E62 F1 F2 F3 F4 F5 F6 F7 F8 F9 F10 F11 F12 F13 F14 F15 F16 F17 F18 F19 F20 F21 F22 F23 F24 F25 F26 F27 F28 F29 F30 F31 F32 F33 F34 F35 F36 F37 F38 F39 F40 F41 F42 F43 F44 F45 F46 F47 F48 F49 F50 F51 F52 F53 F54 F55 F56 F57 F58 F59 F60 F61 F62 G2 G4 G6 G8 G10 G12 G14 G16 G18 G20 G22 G24 G26 G28 G30 G32 G34 G36 G38 G40 G42 G44 G46 G48 G50 G52 G54 G56 G58 G60 Z5 Z7 Z9 Z11 Z13 Z15 Z17 Z19 Z21 Z23 Z25 Z27 Z29 Z31 Z33 Z35 Z37 Z39 Z41 Z43 Z45 Z47 Z49 Z51 Z53 Z55 Z57 Z59 Z61; SLOT19 A1 A2 A3 A4 A19 A61 B1 B2 B3 B4 B61 B62 C1 C2 C3 C4 C62 D1 D2 D3 D4 D19 E1 E2 E3 E4 E19 E62 F1 F2 F3 F4 F62 G2 G4 G6 G8 G10 G12 G14 G16 G18 G20 G22 G24 G26 G28 G30 G32 G34 G36 G38 G40 G42 G44 G46 G48 G50 G52 G54 G56 G58 G60 Z17 Z19 Z37 Z51 Z61; U4 5 6 7 8 13 14 15 16; U44 4; UNK1K1 2 5 6 7; UNK1K2 2 5 6 7; UNK1K3 5 6 7; UNK1K4 5 6 7; UNK1K5 2 5 6 7; UNK1K6 2 5 6 7; UNK1K7 2 5 6 7; UNK1K8 2 7; UNK1K9 2 7; UNK1K10 4 5; UNK1K11 2 5 6 7; UNK1K12 2 5 7; UNK1K13 7; UNK1K14 7; UNK1U1 1 3 5 7 8; UNK2K1 2 5 6 7; UNK2K2 2 5 6 7; UNK2K3 5 6 7; UNK2K4 5 6 7; UNK2K5 2 5 6 7; UNK2K6 2 5 6 7; UNK2K7 2 5 6 7; UNK2K8 2 7; UNK2K9 2 7; UNK2K10 4 5; UNK2K11 2 5 6 7; UNK2K12 2 5 7; UNK2K13 7; UNK2K14 7; UNK2U1 1 3 5 7 8; UNK3K1 2 5 6 7; UNK3K2 2 5 6 7; UNK3K3 5 6 7; UNK3K4 5 6 7; UNK3K5 2 5 6 7; UNK3K6 2 5 6 7; UNK3K7 2 5 6 7; UNK3K8 2 7; UNK3K9 2 7; UNK3K10 4 5; UNK3K11 2 5 6 7; UNK3K12 2 5 7; UNK3K13 7; UNK3K14 7; UNK3U1 1 3 5 7 8; UNK4K1 2 5 6 7; UNK4K2 2 5 6 7; UNK4K3 5 6 7; UNK4K4 5 6 7; UNK4K5 2 5 6 7; UNK4K6 2 5 6 7; UNK4K7 2 5 6 7; UNK4K8 2 7; UNK4K9 2 7; UNK4K10 4 5; UNK4K11 2 5 6 7; UNK4K12 2 5 7; UNK4K13 7; UNK4K14 7; UNK4U1 1 3 5 7 8; UNK5K1 2 5 6 7; UNK5K2 2 5 6 7; UNK5K3 5 6 7; UNK5K4 5 6 7; UNK5K5 2 5 6 7; UNK5K6 2 5 6 7; UNK5K7 2 5 6 7; UNK5K8 2 7; UNK5K9 2 7; UNK5K10 4 5; UNK5K11 2 5 6 7; UNK5K12 2 5 7; UNK5K13 7; UNK5K14 7; UNK5U1 1 3 5 7 8; UNK6K1 2 5 6 7; UNK6K2 2 5 6 7; UNK6K3 5 6 7; UNK6K4 5 6 7; UNK6K5 2 5 6 7; UNK6K6 2 5 6 7; UNK6K7 2 5 6 7; UNK6K8 2 7; UNK6K9 2 7; UNK6K10 4 5; UNK6K11 2 5 6 7; UNK6K12 2 5 7; UNK6K13 7; UNK6K14 7; UNK6U1 1 3 5 7 8; UNK7K1 2 5 6 7; UNK7K2 2 5 6 7; UNK7K3 5 6 7; UNK7K4 5 6 7; UNK7K5 2 5 6 7; UNK7K6 2 5 6 7; UNK7K7 2 5 6 7; UNK7K8 2 7; UNK7K9 2 7; UNK7K10 4 5; UNK7K11 2 5 6 7; UNK7K12 2 5 7; UNK7K13 7; UNK7K14 7; UNK7U1 1 3 5 7 8; UNK8K1 2 5 6 7; UNK8K2 2 5 6 7; UNK8K3 5 6 7; UNK8K4 5 6 7; UNK8K5 2 5 6 7; UNK8K6 2 5 6 7; UNK8K7 2 5 6 7; UNK8K8 2 7; UNK8K9 2 7; UNK8K10 4 5; UNK8K11 2 5 6 7; UNK8K12 2 5 7; UNK8K13 7; UNK8K14 7; UNK8U1 1 3 5 7 8; UNK9K1 2 5 6 7; UNK9K2 2 5 6 7; UNK9K3 5 6 7; UNK9K4 5 6 7; UNK9K5 2 5 6 7; UNK9K6 2 5 6 7; UNK9K7 2 5 6 7; UNK9K8 2 7; UNK9K9 2 7; UNK9K10 4 5; UNK9K11 2 5 6 7; UNK9K12 2 5 7; UNK9K13 7; UNK9K14 7; UNK9U1 1 3 5 7 8; UNK10K1 2 5 6 7; UNK10K2 2 5 6 7; UNK10K3 5 6 7; UNK10K4 5 6 7; UNK10K5 2 5 6 7; UNK10K6 2 5 6 7; UNK10K7 2 5 6 7; UNK10K8 2 7; UNK10K9 2 7; UNK10K10 4 5; UNK10K11 2 5 6 7; UNK10K12 2 5 7; UNK10K13 7; UNK10K14 7; UNK10U1 1 3 5 7 8; UNK11K1 2 5 6 7; UNK11K2 2 5 6 7; UNK11K3 5 6 7; UNK11K4 5 6 7; UNK11K5 2 5 6 7; UNK11K6 2 5 6 7; UNK11K7 2 5 6 7; UNK11K8 2 7; UNK11K9 2 7; UNK11K10 4 5; UNK11K11 2 5 6 7; UNK11K12 2 5 7; UNK11K13 7; UNK11K14 7; UNK11U1 1 3 5 7 8; UNK12K1 2 5 6 7; UNK12K2 2 5 6 7; UNK12K3 5 6 7; UNK12K4 5 6 7; UNK12K5 2 5 6 7; UNK12K6 2 5 6 7; UNK12K7 2 5 6 7; UNK12K8 2 7; UNK12K9 2 7; UNK12K10 4 5; UNK12K11 2 5 6 7; UNK12K12 2 5 7; UNK12K13 7; UNK12K14 7; UNK12U1 1 3 5 7 8; UNK13K1 2 5 6 7; UNK13K2 2 5 6 7; UNK13K3 5 6 7; UNK13K4 5 6 7; UNK13K5 2 5 6 7; UNK13K6 2 5 6 7; UNK13K7 2 5 6 7; UNK13K8 2 7; UNK13K9 2 7; UNK13K10 4 5; UNK13K11 2 5 6 7; UNK13K12 2 5 7; UNK13K13 7; UNK13K14 7; UNK13U1 1 3 5 7 8; UNK14K1 2 5 6 7; UNK14K2 2 5 6 7; UNK14K3 5 6 7; UNK14K4 5 6 7; UNK14K5 2 5 6 7; UNK14K6 2 5 6 7; UNK14K7 2 5 6 7; UNK14K8 2 7; UNK14K9 2 7; UNK14K10 4 5; UNK14K11 2 5 6 7; UNK14K12 2 5 7; UNK14K13 7; UNK14K14 7; UNK14U1 1 3 5 7 8; UNK15K1 2 5 6 7; UNK15K2 2 5 6 7; UNK15K3 5 6 7; UNK15K4 5 6 7; UNK15K5 2 5 6 7; UNK15K6 2 5 6 7; UNK15K7 2 5 6 7; UNK15K8 2 7; UNK15K9 2 7; UNK15K10 4 5; UNK15K11 2 5 6 7; UNK15K12 2 5 7; UNK15K13 7; UNK15K14 7; UNK15U1 1 3 5 7 8; UNK16K1 2 5 6 7; UNK16K2 2 5 6 7; UNK16K3 5 6 7; UNK16K4 5 6 7; UNK16K5 2 5 6 7; UNK16K6 2 5 6 7; UNK16K7 2 5 6 7; UNK16K8 2 7; UNK16K9 2 7; UNK16K10 4 5; UNK16K11 2 5 6 7; UNK16K12 2 5 7; UNK16K13 7; UNK16K14 7; UNK16U1 1 3 5 7 8; UNK038NC-GRIFFI18R-A100 1; UNK730-03146-001_FP-ATE 1; UNK980NC-GRIFFI-1C4 1; UNK* 1; UNK*#2 1

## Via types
v1: diameter 8.5, hole 6.401, TOP to BOTTOM, 1 via

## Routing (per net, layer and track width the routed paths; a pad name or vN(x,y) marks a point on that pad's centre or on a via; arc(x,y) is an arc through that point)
Net_1069:
  vias: v1(223.98,156.49)

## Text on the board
User.40: FIGURE | SIZE | 12.1 | 22.0 | 41.0 | 148.0 | 276.0 | 60.24 | 122.0 | 126.0 | 134.0 | 169.0 | 184.0 | 312.0 | 438.0 | 98.0x87.0 | 180.0x122.0 | DRILL CHART: TOP to BOTTOM | ALL UNITS ARE IN MILS | TOLERANCE | +2.0/-2.0 | +3.0/-1.0 | +3.0/-0.0 | +1.57/-0.0 | +1.0/-2.0 | +3.0/-3.0 | +4.0/-4.0 | PLATED | NON-PLATED | QTY | 128 | 4436 | 1672 | 64 | 4 | 32 | 1 | 20 | 24 | 3
